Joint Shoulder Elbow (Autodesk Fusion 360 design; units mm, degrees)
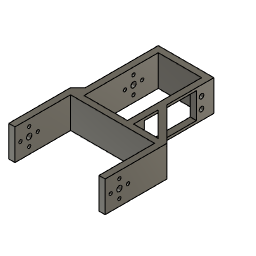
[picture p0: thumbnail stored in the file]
parameter "d5" = 115
sketch "Sketch1" plane through (0, 0, 0) normal (0, 0, 1) x axis (1, 0, 0)
  line L1 (5, 0) -> (0, 0)
  line L2 (78, 0) -> (73, 0)
  line L3 (78, 50) -> (78, 0)
  line L4 (73, 0) -> (73, 57.5)
  line L5 (78, 57.5) -> (5, 57.5)
  line L6 (39, 84) -> (39, 57.5)
  line L7 (78, 50) -> (0, 50)
  line L8 (73, 45) -> (73, 50)
  line L9 (0, 45) -> (73, 45)
  line L10 (5, 50) -> (5, 45)
  line L11 (50.999, 115) -> (45.999, 115)
  line L12 (50.999, 50) -> (50.999, 115)
  line L13 (45.999, 50) -> (50.999, 50)
  line L14 (45.999, 115) -> (45.999, 50)
  line L15 (50.999, 77.001) -> (78, 50)
  line L16 (116.1852, 50) -> (78, 50)
  line L17 (50.999, 69.9299) -> (70.9289, 50)
  line L18 (45.999, 115) -> (6, 115)
  line L19 (45.999, 110) -> (45.999, 115)
  line L20 (6, 110) -> (45.999, 110)
  line L21 (11, 50) -> (6, 50)
  line L22 (11, 115) -> (11, 50)
  line L23 (6, 115) -> (11, 115)
  line L24 (6, 50) -> (6, 115)
  line L25 (0, 0) -> (0, 50)
  line L26 (5, 57.5) -> (5, 0)
  line L27 (6, 75) -> (0, 75)
  line L28 (23, 75) -> (11, 75)
  line L29 (6, 56) -> (0, 50)
  line L30 (8.4853, 50) -> (0, 50)
  point P1 (0, 0)
  point P2 (0, 0)
  point P16 (50.999, 50)
  point P11 (73, 50)
  point P19 (50.999, 77.001)
  point P21 (50.999, 69.9299)
  point P8 (39, 57.5)
  point P7 (73, 57.5)
  point P23 (70.9289, 50)
  point P25 (45.999, 110)
  point P28 (6, 50)
  point P10 (5, 50)
  point P13 (5, 45)
  point P34 (6, 75)
  point P35 (11, 75)
  point P36 (6, 110)
  point P37 (6, 56)
  point P3 (5, 0)
  point P4 (73, 0)
  point P5 (78, 0)
  point P15 (50.999, 115)
  point P29 (11, 50)
  point P31 (6, 115)
  horizontal L1
  vertical L26
  coincident P1 P2
  horizontal L2
  vertical L3
  vertical L4
  perpendicular L4 L5
  perpendicular L5 L6
  horizontal L7
  vertical L8
  horizontal L9
  vertical L10
  horizontal L11
  vertical L12
  horizontal L13
  vertical L14
  coincident L7 P16
  coincident P11 L7
  horizontal L16
  coincident L12 P19
  coincident L12 P21
  coincident L5 P8
  coincident P7 L5
  coincident L7 P23
  horizontal L18
  vertical L19
  horizontal L20
  coincident L14 P25
  perpendicular L26 L27
  horizontal L21
  vertical L22
  horizontal L23
  vertical L24
  coincident L7 P28
  coincident P10 L7
  coincident P13 L9
  coincident L24 P34
  coincident L22 P35
  collinear L27 L28
  coincident L24 P36
  horizontal L30
  coincident L24 P37
  dimension "d4" distance P2 P3 = 5
  dimension "d6" distance P4 P5 = 5 (= "d4")
  dimension "d8" distance L4 L26 = 68
  dimension "d28" distance P10 P11 = 68
  dimension "d29" distance P10 P13 = 5
  dimension "d30" distance P1 L9 = 45
  dimension "d31" distance L4 L12 = 22.001
  dimension "d32" angle L15 L16 = 135
  dimension "d34" distance P15 P16 = 65 (= "d5 - d30 - d29")
  dimension "d54" distance L7 L27 = 25
  dimension "d55" distance P28 P29 = 5
  dimension "d56" distance P28 P31 = 65
  dimension "d58" angle L29 L30 = 45
  dimension "d59" distance L24 L25 = 6
extrude "Extrude1" new body sketch "Sketch1" profile of L1 L26 L25 L2 L3 L4 L7 L8 L9 L10 L11 L12 L13 L14 L15 L17 L18 L19 L20 L21 L22 L23 L24 L29 along normal blind 25
sketch "Sketch2" plane through (0, 0, 0) normal (1, 0, 0) x axis (0, 1, 0)
  line L1 (0, 0) -> (50, 0)
  line L2 (0, 25) -> (0, 0)
  line L3 (50, 25) -> (0, 25)
  line L4 (20, 12.5) -> (0, 12.5)
  line L5 (11.5, 12.5) -> (4.5, 12.5)
  line L6 (50, 0) -> (50, 25)
  circle C1 centre (4.5, 12.5) radius 1.3
  circle C2 centre (11.5, 5.5) radius 1.3
  circle C3 centre (18.5, 12.5) radius 1.3
  circle C4 centre (11.5, 19.5) radius 1.3
  circle C5 centre (11.5, 12.5) radius 2.15
  point P6 (0, 12.5)
  point P8 (4.5, 12.5)
  point P9 (4.5, 12.5)
  point P10 (11.5, 12.5)
  point P14 (11.5, 12.5)
  point P7 (20, 12.5)
  midpoint L2 P6
  perpendicular L2 L4
  coincident L4 P8
  coincident P8 P9
  parallel L4 L5
  coincident P10 P14
  dimension "d13" distance P6 P7 = 20
  dimension "d14" diameter C1 = 2.6
  dimension "d15" distance P9 P10 = 7
  dimension "d18" distance L2 P8 = 4.5
  dimension "d22" diameter C5 = 4.3
  dimension "d17" C-Pattern1-Angle = 360
extrude "Extrude3" cut sketch "Sketch2" profile of C1 C2 C3 C4 C5 along normal blind 78
sketch "Sketch4" plane through (45.999, 0, 0) normal (-1, 0, 0) x axis (0, -1, 0)
  line L1 (-50, 0) -> (-110, 0)
  line L2 (-50, 25) -> (-50, 0)
  line L3 (-110, 25) -> (-50, 25)
  curve K1 (-53.65, 15.044) -> (-53.05, 15.5148)
  line L4 (-60.3, 22.5) -> (-53.65, 22.5)
  curve K2 (-53.65, 6.044) -> (-53.05, 6.5148)
  line L5 (-106.65, 21.9) -> (-106.65, 18.4852)
  curve K3 (-106.65, 15.5148) -> (-106.05, 15.044)
  line L6 (-106.65, 3.1) -> (-106.65, 6.5148)
  line L7 (-53.05, 3.1) -> (-53.05, 6.5148)
  line L8 (-106.65, 9.4852) -> (-106.65, 15.5148)
  line L9 (-53.05, 21.9) -> (-53.05, 18.4852)
  line L10 (-106.65, 18.4852) -> (-106.65, 21.9)
  line L11 (-106.05, 22.5) -> (-99.4, 22.5)
  line L12 (-53.05, 9.4852) -> (-53.05, 15.5148)
  line L13 (-106.05, 2.5) -> (-99.4, 2.5)
  curve K4 (-106.05, 15.044) -> (-106.65, 15.5148)
  line L14 (-60.3, 2.5) -> (-99.4, 2.5)
  curve K5 (-106.65, 6.5148) -> (-106.05, 6.044)
  line L15 (-53.05, 15.5148) -> (-53.05, 9.4852)
  line L16 (-106.65, 15.5148) -> (-106.65, 9.4852)
  line L17 (-53.65, 22.5) -> (-60.3, 22.5)
  line L18 (-99.4, 22.5) -> (-60.3, 22.5)
  line L19 (-99.4, 2.5) -> (-106.05, 2.5)
  curve K6 (-53.65, 18.956) -> (-53.05, 18.4852)
  curve K7 (-53.05, 18.4852) -> (-53.65, 18.956)
  line L20 (-90, 2.5) -> (-65.8578, 2.5)
  line L21 (-60.3, 22.5) -> (-65.8578, 22.5)
  curve K8 (-53.05, 9.4852) -> (-53.65, 9.956)
  line L22 (-65.8578, 22.5) -> (-90, 22.5)
  curve K9 (-106.05, 18.956) -> (-106.65, 18.4852)
  line L23 (-60.3, 2.5) -> (-53.65, 2.5)
  curve K10 (-53.05, 15.5148) -> (-53.65, 15.044)
  curve K11 (-53.05, 6.5148) -> (-53.65, 6.044)
  line L24 (-106.65, 6.5148) -> (-106.65, 3.1)
  line L25 (-53.05, 18.4852) -> (-53.05, 21.9)
  curve K12 (-106.65, 9.4852) -> (-106.05, 9.956)
  line L26 (-65.8578, 2.5) -> (-60.3, 2.5)
  line L27 (-99.4, 2.5) -> (-90, 2.5)
  line L28 (-53.05, 6.5148) -> (-53.05, 3.1)
  curve K13 (-106.05, 9.956) -> (-106.65, 9.4852)
  line L29 (-53.65, 2.5) -> (-60.3, 2.5)
  curve K14 (-53.65, 9.956) -> (-53.05, 9.4852)
  curve K15 (-106.05, 6.044) -> (-106.65, 6.5148)
  curve K16 (-106.65, 18.4852) -> (-106.05, 18.956)
  line L30 (-90, 22.5) -> (-99.4, 22.5)
  line L31 (-99.4, 22.5) -> (-106.05, 22.5)
  line L32 (-50, 12.5) -> (-115, 12.5)
  line L33 (-90, 25) -> (-90, 12.5)
  line L34 (-60.3, 22.5) -> (-99.4, 22.5)
  line L35 (-60.3, 2.5) -> (-60.3, 22.5)
  line L36 (-99.4, 2.5) -> (-60.3, 2.5)
  line L37 (-99.4, 22.5) -> (-99.4, 2.5)
  line L38 (-59.8, 2) -> (-59.8, 23)
  line L39 (-99.9, 2) -> (-59.8, 2)
  line L40 (-99.9, 23) -> (-99.9, 2)
  line L41 (-59.8, 23) -> (-99.9, 23)
  line L42 (-110, 0) -> (-110, 25)
  line L43 (-100.9, 23) -> (-99.9, 23)
  line L44 (-100.9, 2) -> (-100.9, 23)
  line L45 (-99.9, 2) -> (-100.9, 2)
  line L46 (-99.9, 23) -> (-99.9, 2)
  line L47 (-58.8, 23) -> (-59.8, 23)
  line L48 (-58.8, 2) -> (-58.8, 23)
  line L49 (-59.8, 2) -> (-58.8, 2)
  line L50 (-59.8, 23) -> (-59.8, 2)
  arc A1 centre (-54.7, 8) radius 2.22 clockwise from (-53.65, 6.044) to (-53.65, 9.956)
  arc A2 centre (-105, 17) radius 2.22 clockwise from (-106.05, 18.956) to (-106.05, 15.044)
  arc A3 centre (-54.7, 17) radius 2.22 clockwise from (-53.65, 15.044) to (-53.65, 18.956)
  circle C1 centre (-90, 12.5) radius 3.292
  arc A4 centre (-105, 17) radius 2.22 clockwise from (-106.05, 18.956) to (-106.05, 15.044)
  arc A5 centre (-105, 8) radius 2.22 clockwise from (-106.05, 9.956) to (-106.05, 6.044)
  circle C2 centre (-90, 12.5) radius 1.3
  arc A6 centre (-54.7, 8) radius 2.22 clockwise from (-53.65, 6.044) to (-53.65, 9.956)
  arc A7 centre (-54.7, 17) radius 2.22 clockwise from (-53.65, 15.044) to (-53.65, 18.956)
  arc A8 centre (-105, 8) radius 2.22 clockwise from (-106.05, 9.956) to (-106.05, 6.044)
  circle C3 centre (-105, 17) radius 1.85
  circle C4 centre (-105, 8) radius 1.85
  circle C5 centre (-54.7, 8) radius 1.85
  circle C6 centre (-54.7, 17) radius 1.85
  point P77 (-50, 12.5)
  point P78 (-90, 12.5)
  point P79 (-90, 25)
  point P37 (-60.3, 2.5)
  point P86 (-60.3, 2.5)
  point P74 (-99.4, 22.5)
  point P84 (-99.4, 22.5)
  point P91 (-99.9, 23)
  point P92 (-100.9, 23)
  point P94 (-99.9, 2)
  point P88 (-59.8, 23)
  point P95 (-58.8, 23)
  point P97 (-59.8, 2)
  midpoint L2 P77
  coincident L32 P78
  coincident L3 P79
  perpendicular L3 L33
  concentric A4 C3
  concentric A8 C4
  concentric A6 C5
  concentric A7 C6
  horizontal L34
  vertical L35
  horizontal L36
  vertical L37
  coincident P37 P86
  coincident P74 P84
  horizontal L43
  vertical L44
  horizontal L45
  vertical L46
  horizontal L47
  vertical L48
  horizontal L49
  vertical L50
  dimension "d35" distance L2 L33 = 40
  dimension "d36" diameter C3 = 3.7
  dimension "d37" diameter C6 = 3.7 (= "d36")
  dimension "d38" diameter C5 = 3.7 (= "d36")
  dimension "d39" diameter C4 = 3.7 (= "d36")
  dimension "d42" = -0.5
  dimension "d50" distance P91 P92 = 1
  dimension "d51" distance P91 P94 = 21
  dimension "d52" distance P88 P95 = 1
  dimension "d53" distance P88 P97 = 21
extrude "Extrude4" cut sketch "Sketch4" profile of C3 C4 C5 C6 L34 L35 L36 L37 L38 L39 L40 L41 L43 L44 L45 L46 L47 L48 L49 L50 to an object
sketch "Sketch5" plane through (78, 0, 0) normal (1, 0, 0) x axis (0, 1, 0)
  line L1 (50, 0) -> (0, 0)
  line L2 (50, 25) -> (50, 0)
  line L3 (0, 25) -> (50, 25)
  line L4 (0, 0) -> (0, 25)
  line L5 (77.001, 25) -> (77.001, 23)
  line L6 (50, 25) -> (77.001, 25)
  line L7 (50, 0) -> (50, 25)
  line L8 (77.001, 0) -> (50, 0)
  line L9 (77.001, 2) -> (77.001, 0)
  line L10 (50, 22.5) -> (60.3, 22.5)
  line L11 (50, 2.5) -> (50, 22.5)
  line L12 (60.3, 2.5) -> (50, 2.5)
  line L13 (60.3, 22.5) -> (60.3, 2.5)
  line L14 (50, 23) -> (60.3, 23)
  line L15 (60.3, 2) -> (50, 2)
  line L16 (60.3, 2) -> (60.3, 23)
  line L17 (58.8, 2) -> (77.001, 2)
  line L18 (58.8, 23) -> (58.8, 2)
  line L19 (77.001, 23) -> (58.8, 23)
  circle C1 centre (11.5, 12.5) radius 2.15
  circle C2 centre (4.5, 12.5) radius 1.3
  circle C3 centre (11.5, 5.5) radius 1.3
  circle C4 centre (11.5, 19.5) radius 1.3
  circle C5 centre (18.5, 12.5) radius 1.3
  circle C6 centre (54.7, 17) radius 1.85
  circle C7 centre (54.7, 17) radius 1.85
  circle C8 centre (54.7, 8) radius 1.85
  point P20 (60.3, 22.5)
  point P21 (50, 22.5)
  point P23 (60.3, 2.5)
  horizontal L10
  vertical L11
  horizontal L12
  vertical L13
  perpendicular L15 L16
  dimension "d43" distance P20 P21 = 10.3
  dimension "d44" distance P20 P23 = 20
  dimension "d48" = 0.5
  dimension "d49" = 0.5
extrude "Extrude5" cut sketch "Sketch5" profile of L2 C6 L7 C7 C8 L10 L11 L12 L13 L14 L15 L16 to an object
sketch "Sketch6" plane through (6, 0, 0) normal (-1, 0, 0) x axis (0, -1, 0)
  line L1 (-56, 0) -> (-115, 0)
  line L2 (-56, 25) -> (-56, 0)
  line L3 (-115, 25) -> (-56, 25)
  line L4 (-115, 0) -> (-115, 25)
  line L5 (-90, 12.5) -> (-97, 12.5)
  circle C1 centre (-83, 12.5) radius 1.3
  circle C2 centre (-97, 12.5) radius 1.3
  circle C3 centre (-90, 19.5) radius 1.3
  circle C4 centre (-90, 12.5) radius 2.15
  circle C5 centre (-90, 5.5) radius 1.3
  point P7 (-97, 12.5)
  point P10 (-97, 12.5)
  point P8 (-90, 12.5)
  point P12 (-90, 12.5)
  coincident P7 P10
  coincident P8 P12
  dimension "d62" diameter C2 = 2.6
  dimension "d63" distance P10 P12 = 7
  dimension "d64" diameter C4 = 4.3
extrude "Extrude6" cut sketch "Sketch6" profile of C1 C2 C3 C4 C5 to an object
extrude "Extrude2" cut sketch "Sketch2" profile of C1 C2 C3 C4 C5 no distance stored
move "Move1" RotateAngle -180
move "Move2"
